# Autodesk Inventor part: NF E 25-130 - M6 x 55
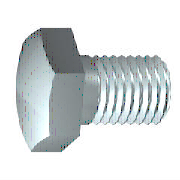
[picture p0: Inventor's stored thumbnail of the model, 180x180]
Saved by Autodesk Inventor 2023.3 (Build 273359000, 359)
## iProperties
IsCustomPart: 0
Created: 2022-02
Part Number: NF E 25-130 - M6 x 55
Material: Acier, doux
Description: Vis avec rondelle cuvette emboutie. Produit de classe A.
Document SubType Name: Modeling
Standard: NF E 25-130
Designer: Thier
Standards Organization: AFNOR
Language: fr-FR
Size Designation: M6 x 55
Categories: <MemberInstance><Categories><Category DisplayName="Visserie" InternalName="e4da775c-781d-43d5-af7c-5136215cf5a6" Mnemonic="FSTN"><Category DisplayName="Vis" Int
Density: 7.85 g/cm^3
Appearance: Semi-poli
Author: Thier
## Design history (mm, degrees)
sketch "Esquisse1"
  geometry: L1 (0, 4.44)-(0, 2.387); L2 (4.5, 3)-(55, 3); L3 (55, 3)-(55, 0); L4 (55, 0)-(-0.5, 0); L5 (-11.6, 0)-(66.1, 0) reference; L6 (-0.5, 0)-(-0.5, 4.44); L7 (-0.5, 4.44)-(0, 4.44); L8 (4.5, 3)-(3.886, 2.387); L9 (3.886, 2.387)-(0, 2.387); L10 (0, -0.888)-(0, 5.328) reference
  constraints: 16 end point, 2 collinear, 2 perpendicular, 1 parallel
  dimensions: "d0" = 55 distance between parallel lines of L3 L1 (= NLG); "d1" = 50.5 distance from line of L2.start L3 (= GEL); "d2" = 6 diameter of L2 L4 (= GD); "d9" = 0.5001 distance between parallel lines of L6 L1 (computed from SD); "d10" = 8.88 diameter of L7 L4 (= SD2); "d13" = 0.61355 horizontal distance of L2.start L8.end (computed from GAL); "d14" = 4.7731 diameter of L9 L4 (= BDM)
revolve "Corps" sketch "Esquisse1" stored, may be unused: angle "d12" = 90 deg
sketch "Esquisse2"
  geometry: L1 (0, 5.774)-(5, 2.887); L2 (5, 2.887)-(5, -2.887); L3 (5, -2.887)-(0, -5.774); L4 (0, -5.774)-(-5, -2.887); L5 (-5, -2.887)-(-5, 2.887); L6 (-5, 2.887)-(0, 5.774); 2 further points
  constraints: 12 end point, 1 coincident, 1 vertical, 11 other
  dimensions: "d11" = 10 distance between parallel lines of L5 L2 (= SW)
extrude "Tête" join sketch "Esquisse2" distance "d3" = 3.5 (= KOH - SD); taper "d4" = 0 deg
sketch "Esquisse4"
  geometry: L1 (-4, 5)-(-4, 5.774); L2 (-4, 5.774)-(-3.554, 5.774); L3 (-3.554, 5.774)-(-4, 5); L4 (-4.7, 0)-(0.2, 0) reference; L5 (-0.5, 5.774)-(-4, 5.774) reference; L6 (-4, 2.887)-(-4, 5.774) reference
  constraints: 6 end point, 2 collinear, 1 perpendicular, 1 vertical
  dimensions: "d5" = 30 deg angle of L3 L1 (= ANG1); "d19" = 10 diameter of L1.start L4 (= SW0)
revolve "Chanfrein1" sketch "Esquisse4" stored, may be unused: angle "d21" = 90 deg
workplane "Work Plane1"
body "Solid1"
feature "Filetage" dims "d15" = 50.5 (= GEL), "d16" = 0
chamfer "Chanfrein2" distance "d6" = 0.61345 (= -0.5 x SPD + 0.5 x GD); stored, may be unused: second distance "d7" = 0.61355 (computed from GUL), angle "d55" = 45 deg
other parameters: "NLG" = 55 [user parameter; used in 1 equation term], "GD" = 6 (= NND) [user parameter; used in 2 equation terms], "BDM" = 4.7731 (= SPD) [user parameter; used in 1 equation term], "KOH" = 4 [user parameter; used in 1 equation term], "GEL" = 50.5 [user parameter; used in 2 equation terms], "SW" = 10 [user parameter; used in 3 equation terms], "SW0" = 10 (= SW) [user parameter; used in 1 equation term], "SPD" = 4.7731 [user parameter; used in 2 equation terms], "SD2" = 8.88 [user parameter; used in 2 equation terms], "SD" = 0.5 [user parameter; used in 2 equation terms], "ANG1" = 30 deg [user parameter; used in 1 equation term], "GAL" = 0.61345 (= 0.61345 x PTC) [user parameter; used in 1 equation term], "GUL" = 0.61345 (= 0.61345 x PTC) [user parameter; used in 1 equation term], "d8" = 0, "RR" = 0.25 [user parameter], "d57" = 0, "d58" = 0, "GD1" = 4.7731 (= THREADDIA - 1.2269 x PTC) [user parameter], "THREADDIA" = 6 [user parameter; used in 1 equation term], "SDH" = 8.88 (= SD2) [user parameter], "TOA" = 30 deg [user parameter], "PTC" = 1 [user parameter; used in 4 equation terms], "NND" = 6 [user parameter; used in 1 equation term], "E0" = 11.55 (= 1.155 x SW) [user parameter]
